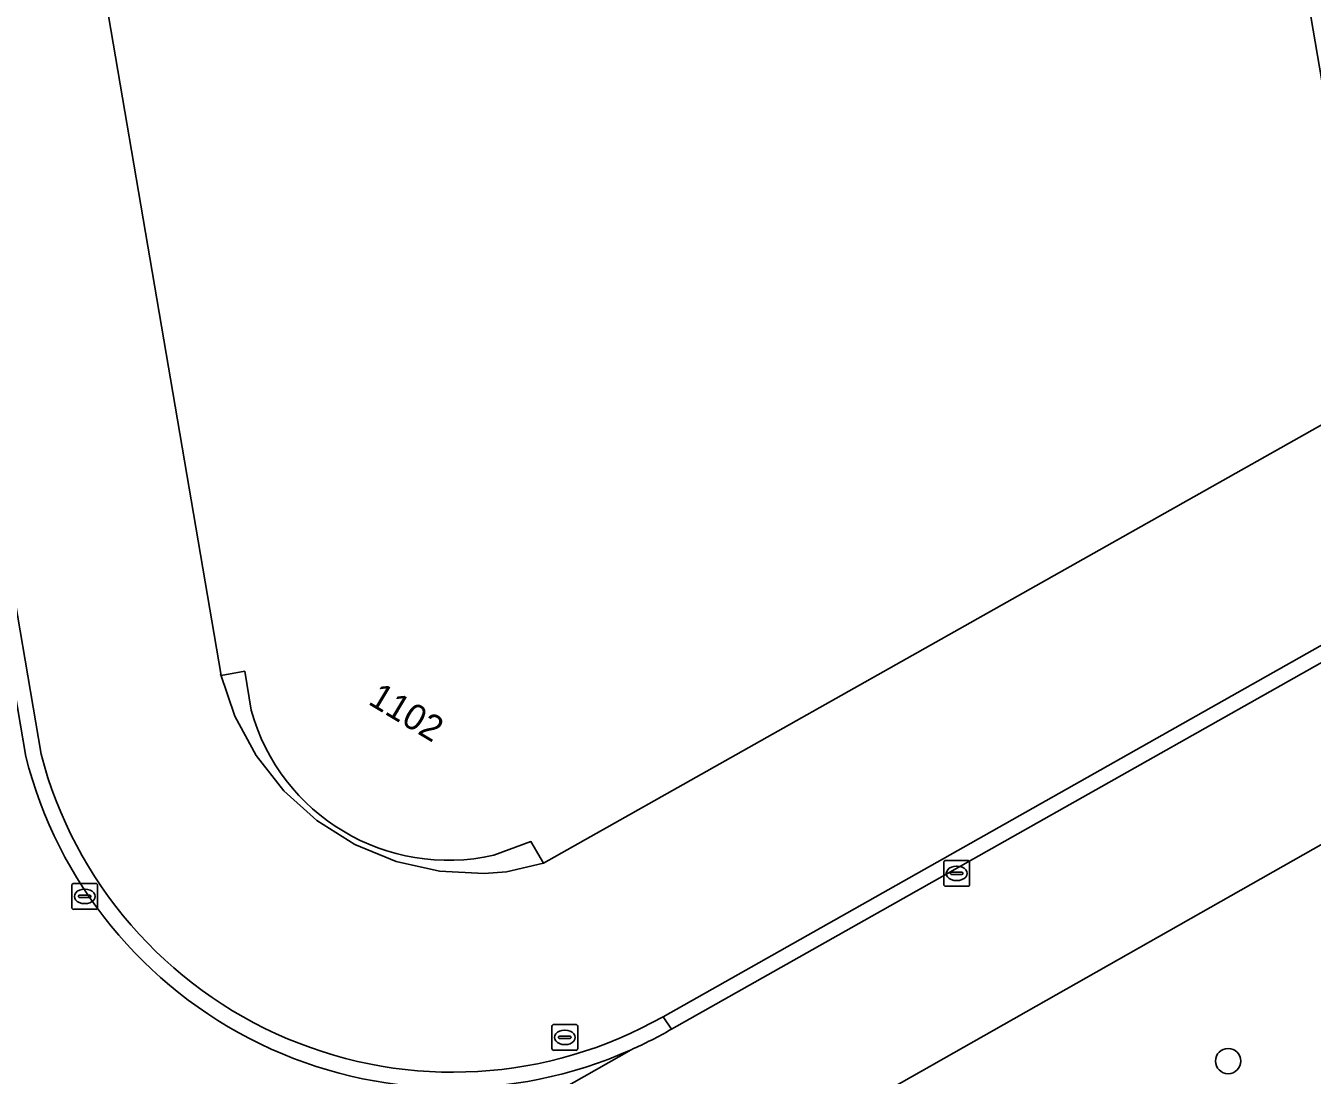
# Model space of a CAD drawing. Extents: x 154324 to 155744, y 382937 to 384188.
# Drawn here: x 154961.84 to 155011.62, y 383207.07 to 383247.67 of the extents above; entities that cross this region are included whole.
import ezdxf

# ---------------------------------------------------------------- set-up
doc = ezdxf.new("R2010")
doc.units = 0
for name, color, linetype in [('IMGEO_Berm_groen', 7, 'Continuous'), ('IMGEO_Boom', 7, 'Continuous'), ('IMGEO_Brandkraan', 7, 'Continuous'), ('IMGEO_Kolk', 7, 'Continuous'), ('IMGEO_Pand', 7, 'Continuous'), ('IMGEO_Pand_nummerreeks', 7, 'Continuous'), ('IMGEO_Pand_overbouw', 7, 'Continuous'), ('IMGEO_Parkeervlak_open', 7, 'Continuous'), ('IMGEO_Rijbaan_lokaal_gesloten', 7, 'Continuous'), ('IMGEO_Rijbaan_lokaal_open', 7, 'Continuous')]:
    doc.layers.add(name, color=color, linetype=linetype)

msp = doc.modelspace()

# ---------------------------------------------------------------- linework, layer by layer
at = {"layer": 'IMGEO_Berm_groen'}
msp.add_lwpolyline([(155055.755, 383240.815), (155027.965, 383225.065), (154995.341, 383206.576), (154995.355, 383206.151)], dxfattribs=at)
at = {"layer": 'IMGEO_Boom'}
msp.add_circle((155008.362, 383207.619), 0.489, dxfattribs=at)
at = {"layer": 'IMGEO_Brandkraan'}
for p, q in [((154982.195, 383208.108), (154982.195, 383208.96)), ((154982.27, 383209.034), (154983.122, 383209.034)), ((154983.196, 383208.96), (154983.196, 383208.108)), ((154982.454, 383208.528), (154982.454, 383208.54)), ((154982.892, 383208.491), (154982.494, 383208.491)), ((154982.497, 383208.577), (154982.895, 383208.577)), ((154982.683, 383208.814), (154982.708, 383208.814)), ((154982.938, 383208.54), (154982.938, 383208.528)), ((154983.122, 383208.034), (154982.27, 383208.034)), ((154982.706, 383208.254), (154982.681, 383208.254))]:
    msp.add_line(p, q, dxfattribs=at)
for points in [[(154982.195, 383208.108), (154982.195, 383208.96)], [(154982.27, 383209.034), (154983.122, 383209.034)], [(154983.196, 383208.96), (154983.196, 383208.108)], [(154983.122, 383208.034), (154982.27, 383208.034)]]:
    msp.add_lwpolyline(points, dxfattribs=at)
for centre, radius, start, end in [((154982.272, 383208.958), 0.0765, 91.552, 178.448), ((154982.272, 383208.958), 0.0765, 91.552, 178.448), ((154983.12, 383208.958), 0.0765, 1.552, 88.448), ((154983.12, 383208.958), 0.0765, 1.552, 88.448), ((154982.494, 383208.537), 0.0403, 85.8775, 175.7526), ((154982.491, 383208.527), 0.0366, 178.938, 274.7102), ((154982.895, 383208.534), 0.043, 264.8664, 352.4533), ((154982.899, 383208.539), 0.0386, 1.7309, 96.639), ((154982.272, 383208.11), 0.0765, 181.552, 268.448), ((154982.272, 383208.11), 0.0765, 181.552, 268.448), ((154983.12, 383208.11), 0.0765, 271.552, 358.448), ((154983.12, 383208.11), 0.0765, 271.552, 358.448)]:
    msp.add_arc(centre, radius, start, end, dxfattribs=at)
for centre, major_axis, ratio, start_param, end_param in [((154982.682, 383208.534), (-0.387, 0.002), 0.722429, 4.712389, 7.853982), ((154982.707, 383208.534), (-0.39, 0.002), 0.717154, 1.570796, 4.712389)]:
    msp.add_ellipse(centre, major_axis=major_axis, ratio=ratio, start_param=start_param, end_param=end_param, dxfattribs=at)
at = {"layer": 'IMGEO_Kolk'}
for p, q in [((154997.433, 383215.38), (154998.285, 383215.38)), ((154997.358, 383214.454), (154997.358, 383215.306)), ((154997.617, 383214.874), (154997.617, 383214.886)), ((154997.66, 383214.923), (154998.058, 383214.923)), ((154997.846, 383215.16), (154997.871, 383215.16)), ((154998.101, 383214.886), (154998.101, 383214.874)), ((154998.359, 383215.306), (154998.359, 383214.454)), ((154963.617, 383213.563), (154963.617, 383214.415)), ((154963.692, 383214.489), (154964.544, 383214.489)), ((154964.618, 383214.415), (154964.618, 383213.563)), ((154998.285, 383214.38), (154997.433, 383214.38)), ((154998.055, 383214.837), (154997.657, 383214.837)), ((154997.869, 383214.6), (154997.844, 383214.6)), ((154963.876, 383213.983), (154963.876, 383213.995)), ((154964.314, 383213.946), (154963.916, 383213.946)), ((154963.919, 383214.032), (154964.317, 383214.032)), ((154964.105, 383214.269), (154964.13, 383214.269)), ((154964.36, 383213.995), (154964.36, 383213.983)), ((154964.544, 383213.489), (154963.692, 383213.489)), ((154964.128, 383213.709), (154964.103, 383213.709))]:
    msp.add_line(p, q, dxfattribs=at)
for points in [[(154997.433, 383215.38), (154998.285, 383215.38)], [(154997.358, 383214.454), (154997.358, 383215.306)], [(154998.359, 383215.306), (154998.359, 383214.454)], [(154963.617, 383213.563), (154963.617, 383214.415)], [(154963.692, 383214.489), (154964.544, 383214.489)], [(154964.618, 383214.415), (154964.618, 383213.563)], [(154998.285, 383214.38), (154997.433, 383214.38)], [(154964.544, 383213.489), (154963.692, 383213.489)]]:
    msp.add_lwpolyline(points, dxfattribs=at)
for centre, radius, start, end in [((154997.435, 383215.304), 0.0765, 91.552, 178.448), ((154997.435, 383215.304), 0.0765, 91.552, 178.448), ((154998.283, 383215.304), 0.0765, 1.552, 88.448), ((154998.283, 383215.304), 0.0765, 1.552, 88.448), ((154997.657, 383214.883), 0.0403, 85.8775, 175.7526), ((154997.654, 383214.873), 0.0366, 178.938, 274.7102), ((154998.058, 383214.88), 0.043, 264.8664, 352.4533), ((154998.062, 383214.885), 0.0386, 1.7309, 96.639), ((154963.694, 383214.413), 0.0765, 91.552, 178.448), ((154963.694, 383214.413), 0.0765, 91.552, 178.448), ((154964.542, 383214.413), 0.0765, 1.552, 88.448), ((154964.542, 383214.413), 0.0765, 1.552, 88.448), ((154997.435, 383214.456), 0.0765, 181.552, 268.448), ((154997.435, 383214.456), 0.0765, 181.552, 268.448), ((154998.283, 383214.456), 0.0765, 271.552, 358.448), ((154998.283, 383214.456), 0.0765, 271.552, 358.448), ((154963.916, 383213.992), 0.0403, 85.8775, 175.7526), ((154963.913, 383213.982), 0.0366, 178.938, 274.7102), ((154964.317, 383213.989), 0.043, 264.8664, 352.4533), ((154964.321, 383213.994), 0.0386, 1.7309, 96.639), ((154963.694, 383213.565), 0.0765, 181.552, 268.448), ((154963.694, 383213.565), 0.0765, 181.552, 268.448), ((154964.542, 383213.565), 0.0765, 271.552, 358.448), ((154964.542, 383213.565), 0.0765, 271.552, 358.448)]:
    msp.add_arc(centre, radius, start, end, dxfattribs=at)
for centre, major_axis, ratio, start_param, end_param in [((154997.845, 383214.88), (-0.387, 0.002), 0.722429, 4.712389, 7.853982), ((154997.87, 383214.88), (-0.39, 0.002), 0.717154, 1.570796, 4.712389), ((154964.104, 383213.989), (-0.387, 0.002), 0.722429, 4.712389, 7.853982), ((154964.129, 383213.989), (-0.39, 0.002), 0.717154, 1.570796, 4.712389)]:
    msp.add_ellipse(centre, major_axis=major_axis, ratio=ratio, start_param=start_param, end_param=end_param, dxfattribs=at)
at = {"layer": 'IMGEO_Pand'}
msp.add_lwpolyline([(154979.95, 383215.582), (154981.386, 383216.111), (154981.866, 383215.269), (155014.059, 383233.409), (155007.491, 383271.866), (154962.295, 383264.145), (154969.397, 383222.533), (154970.312, 383222.697), (154970.556, 383221.2)], dxfattribs=at)
msp.add_arc((154978.191, 383223.304), 7.919, 195.404, 282.8337, dxfattribs=at)
at = {"layer": 'IMGEO_Pand_overbouw'}
for points in [[(154970.556, 383221.2), (154970.312, 383222.697), (154969.397, 383222.533), (154969.373, 383222.594), (154969.926, 383220.957), (154970.749, 383219.437), (154971.819, 383218.079), (154973.104, 383216.923), (154974.566, 383216.002), (154976.164, 383215.342), (154977.851, 383214.964), (154979.577, 383214.878), (154980.44, 383214.946), (154981.866, 383215.269)], [(154981.866, 383215.269), (154981.386, 383216.111), (154979.95, 383215.582)]]:
    msp.add_lwpolyline(points, dxfattribs=at)
msp.add_arc((154978.191, 383223.304), 7.919, 195.404, 282.8337, dxfattribs=at)
at = {"layer": 'IMGEO_Parkeervlak_open'}
for points in [[(154970.556, 383221.2), (154970.312, 383222.697), (154969.397, 383222.533), (154962.295, 383264.145), (154961.04, 383271.548), (154956.449, 383298.428), (154954.479, 383309.839), (154953.555, 383315.462), (154952.604, 383321.047), (154948.75, 383343.779), (154944.993, 383365.869), (154944.925, 383366.268), (154965.468, 383369.782), (154964.539, 383375.316), (154941.3, 383371.33), (154939.601, 383371.039), (154936.699, 383370.542), (154936.71, 383370.477), (154937.698, 383364.674), (154938.491, 383360.02), (154942.478, 383336.616), (154962.428, 383219.494)], [(155020.911, 383228.747), (155019.588, 383236.524), (155014.059, 383233.409), (154981.866, 383215.269), (154981.386, 383216.111), (154979.95, 383215.582)], [(154986.496, 383209.335), (155020.911, 383228.747)]]:
    msp.add_lwpolyline(points, dxfattribs=at)
for centre, radius, start, end in [((154978.191, 383223.304), 7.919, 195.404, 282.8337), ((154978.364, 383223.659), 16.471, 194.647, 299.5842)]:
    msp.add_arc(centre, radius, start, end, dxfattribs=at)
at = {"layer": 'IMGEO_Rijbaan_lokaal_gesloten'}
for points in [[(154961.836, 383219.4), (154937.891, 383359.922), (154875.734, 383724.688)], [(155052.703, 383246.003), (154986.821, 383208.849)], [(154710.177, 383044.63), (154781.163, 383085.993), (154788.616, 383090.336), (154796.646, 383095.015), (154799.353, 383096.592), (154807.406, 383100.983), (154807.99, 383101.454), (154870.558, 383136.478), (154922.655, 383165.821), (154972.989, 383194.067), (154988.643, 383202.929), (154991.288, 383204.465), (154991.527, 383204.587), (154994.571, 383206.14), (154995.341, 383206.576), (155027.965, 383225.065), (155055.755, 383240.815)], [(154985.26, 383208.054), (154967.732, 383198.105), (154950.17, 383188.22), (154949.49, 383187.837), (154947.078, 383186.481), (154867.234, 383141.522), (154850.148, 383131.904), (154814.791, 383112.011)], [(154950.17, 383188.22), (154967.732, 383198.105), (154985.26, 383208.054)]]:
    msp.add_lwpolyline(points, dxfattribs=at)
for centre, radius, start, end in [((154978.33, 383223.599), 17.02, 194.2823, 294.0289), ((154978.183, 383223.88), 17.336, 294.0931, 299.8854)]:
    msp.add_arc(centre, radius, start, end, dxfattribs=at)
at = {"layer": 'IMGEO_Rijbaan_lokaal_open'}
for points in [[(154938.491, 383360.02), (154937.891, 383359.922), (154961.836, 383219.4)], [(154962.428, 383219.494), (154942.478, 383336.616), (154938.491, 383360.02)], [(155052.433, 383246.528), (155020.911, 383228.747), (154986.496, 383209.335), (154986.821, 383208.849), (155052.703, 383246.003)], [(154986.821, 383208.849), (154986.496, 383209.335)]]:
    msp.add_lwpolyline(points, dxfattribs=at)
for centre, radius, start, end in [((154978.33, 383223.599), 17.02, 194.2823, 294.0289), ((154978.364, 383223.659), 16.471, 194.647, 299.5842), ((154978.183, 383223.88), 17.336, 294.0931, 299.8854)]:
    msp.add_arc(centre, radius, start, end, dxfattribs=at)

# ---------------------------------------------------------------- texts
at = {"layer": 'IMGEO_Pand_nummerreeks'}
msp.add_text('1102', height=1, rotation=329.1183, dxfattribs=at).set_placement((154975.044, 383221.452))

doc.saveas('drawing.dxf')
